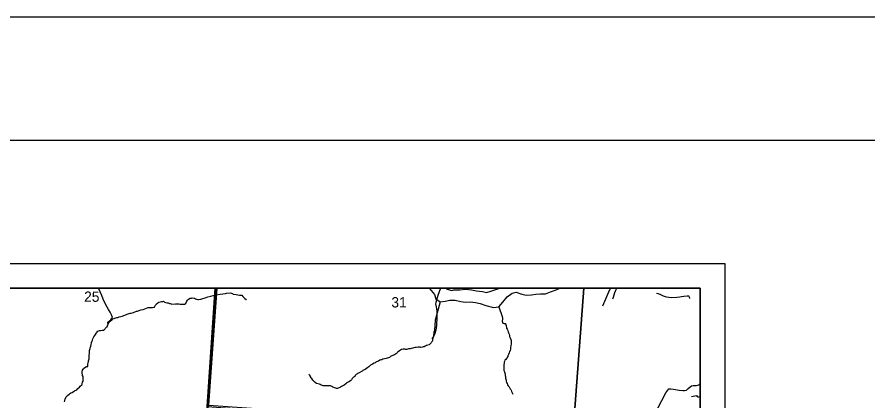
# Model space of a CAD drawing. Extents: x 0 to 34, y 0 to 22.
# Drawn here: x 6.132 to 9.58, y 20.443 to 22 of the extents above; entities that cross this region are included whole.
import ezdxf

# ---------------------------------------------------------------- set-up
doc = ezdxf.new("R2010")
doc.units = 0
for name, color, linetype in [('GM_X_Corporation', 7, 'Continuous'), ('GM_X_County_Road', 7, 'Continuous'), ('GM_X_Minor_River', 7, 'Continuous'), ('GM_X_Section_Text', 7, 'Continuous'), ('GM_X_Township_Road', 7, 'Continuous'), ('SH_Border', 7, 'Continuous'), ('SH_Data', 7, 'Continuous')]:
    doc.layers.add(name, color=color, linetype=linetype)

msp = doc.modelspace()

# ---------------------------------------------------------------- linework, layer by layer
at = {"layer": 'GM_X_Corporation'}
for points in [[(3.3441, 14.1), (8.9, 14.1), (8.9, 20.9), (2.1, 20.9), (2.1, 16.1353), (2.1457, 16.065), (2.3447, 15.6926), (2.4297, 15.5215), (2.465, 15.4504), (2.4884, 15.4033), (2.5769, 15.2135), (2.7849, 14.8403), (2.8931, 14.6544), (3.0297, 14.4867), (3.1386, 14.3654), (3.228, 14.2415)], [(6.9348, 20.9), (2.1, 20.9), (2.1, 19.6396), (2.105, 19.6393), (2.5886, 19.6074), (3.0215, 19.5789), (3.8201, 19.5262), (3.8692, 19.5228), (4.8375, 19.4557), (5.0201, 19.4401), (5.6539, 19.3859), (5.9419, 19.3649), (6.5423, 19.3229), (6.824, 19.3005), (6.835, 19.4037), (6.8961, 20.3303), (6.9032, 20.4198)], [(6.9414, 20.9), (5.9334, 20.9), (5.901, 20.4176), (6.9011, 20.3385), (6.9084, 20.4264)], [(8.9, 20.2763), (8.9, 20.9), (6.9348, 20.9), (6.9032, 20.4198), (8.0028, 20.34), (8.3805, 20.3169), (8.59, 20.3005)], [(8.4295, 20.9), (6.9414, 20.9), (6.9084, 20.4264), (8.0074, 20.3484), (8.3851, 20.3217)], [(8.9, 20.285), (8.9, 20.9), (8.4295, 20.9), (8.3851, 20.3217)]]:
    msp.add_lwpolyline(points, close=True, dxfattribs=at)
at = {"layer": 'GM_X_County_Road'}
for points in [[(7.8703, 20.9), (7.8765, 20.8966), (7.8924, 20.8915), (7.8984, 20.8923)], [(7.8984, 20.8923), (7.9024, 20.8929), (7.9271, 20.894), (7.9499, 20.8959), (7.9735, 20.8936), (7.9943, 20.889), (8.0183, 20.8863), (8.0342, 20.8825), (8.0528, 20.8875), (8.0718, 20.8947), (8.0894, 20.9)], [(8.6142, 20.3116), (8.6222, 20.3154), (8.6587, 20.3383), (8.6939, 20.3635), (8.7082, 20.3797), (8.7282, 20.4138), (8.7614, 20.4759), (8.774, 20.4915)], [(8.774, 20.4915), (8.7814, 20.4925), (8.7928, 20.4907), (8.8157, 20.4862), (8.8297, 20.485), (8.8368, 20.485), (8.8451, 20.4869), (8.8513, 20.4928), (8.8593, 20.5008), (8.8653, 20.5044), (8.8722, 20.5057), (8.8852, 20.5062), (8.895, 20.5088), (8.9, 20.5135)]]:
    msp.add_lwpolyline(points, dxfattribs=at)
at = {"layer": 'GM_X_Minor_River'}
for points in [[(6.5013, 20.7528), (6.5009, 20.7625), (6.5123, 20.7715), (6.5194, 20.781), (6.5153, 20.7916), (6.5092, 20.803), (6.5036, 20.8132), (6.4979, 20.8231), (6.4877, 20.8409), (6.4816, 20.856), (6.476, 20.8708), (6.4691, 20.8856), (6.4631, 20.9)], [(7.8029, 20.9), (7.8102, 20.8915), (7.8238, 20.874), (7.829, 20.8565), (7.8464, 20.8451), (7.8669, 20.8473), (7.8858, 20.8518), (7.9078, 20.8518), (7.9304, 20.8464), (7.9494, 20.8433), (7.9683, 20.8448), (7.9902, 20.8424), (8.0091, 20.8378), (8.0318, 20.8302), (8.0628, 20.8225), (8.084, 20.824), (8.1007, 20.8429), (8.119, 20.8656), (8.138, 20.8799), (8.1554, 20.8837), (8.1781, 20.8753), (8.1955, 20.8722), (8.2174, 20.8729), (8.2348, 20.8766), (8.2538, 20.8773)], [(8.2538, 20.8773), (8.2742, 20.878), (8.2939, 20.8855), (8.3166, 20.8938), (8.3313, 20.9)], [(8.5061, 20.8284), (8.5348, 20.8945), (8.5396, 20.9)], [(6.7301, 20.844), (6.7402, 20.8408), (6.7448, 20.8403), (6.7497, 20.8387), (6.7527, 20.8375), (6.7572, 20.8363), (6.7598, 20.8359), (6.775, 20.8368), (6.7886, 20.8365), (6.7935, 20.8353), (6.7966, 20.8349), (6.8026, 20.8348), (6.8121, 20.8357), (6.8152, 20.8372), (6.8182, 20.8402), (6.821, 20.8477), (6.8234, 20.8511), (6.8269, 20.8556), (6.8341, 20.8593), (6.8391, 20.8604), (6.8417, 20.8607), (6.8512, 20.8594), (6.8553, 20.8574), (6.859, 20.8555), (6.8651, 20.8546), (6.8681, 20.8545), (6.8768, 20.8555), (6.8807, 20.857), (6.8986, 20.8624), (6.905, 20.8645), (6.9172, 20.8685), (6.9275, 20.8702), (6.9347, 20.872), (6.94, 20.8738), (6.956, 20.8766), (6.9769, 20.8793), (6.9811, 20.8807), (6.9955, 20.8809), (7.0019, 20.8796), (7.0049, 20.8792), (7.0087, 20.8765), (7.02, 20.8744), (7.0343, 20.8722), (7.043, 20.8721), (7.0471, 20.8667), (7.056, 20.8578), (7.0609, 20.8539), (7.0618, 20.8534)], [(6.3966, 20.5113), (6.397, 20.5139), (6.3982, 20.5188), (6.3998, 20.5234), (6.4011, 20.5305), (6.4011, 20.534), (6.4005, 20.5393), (6.3998, 20.5423), (6.3983, 20.5458), (6.3976, 20.55), (6.3965, 20.5527), (6.3958, 20.5557), (6.3963, 20.561), (6.3975, 20.5671), (6.401, 20.5719), (6.4015, 20.5746), (6.4068, 20.5779), (6.4145, 20.5824), (6.419, 20.5827), (6.4195, 20.5853), (6.4196, 20.5914), (6.4212, 20.5986), (6.4216, 20.602), (6.4225, 20.6058), (6.4233, 20.6092), (6.4241, 20.6141), (6.425, 20.6179), (6.4251, 20.627), (6.4257, 20.6368), (6.4261, 20.6399), (6.4266, 20.6478), (6.4283, 20.655), (6.4291, 20.6577), (6.4299, 20.6607), (6.4311, 20.6656), (6.4323, 20.6721), (6.4343, 20.677), (6.4348, 20.68), (6.4372, 20.6872), (6.4376, 20.6898), (6.4396, 20.6951), (6.4427, 20.7004), (6.4435, 20.703), (6.4474, 20.7079), (6.4509, 20.712), (6.4532, 20.7161), (6.4544, 20.7192), (6.4598, 20.7263), (6.4667, 20.7284), (6.4705, 20.7291), (6.478, 20.7294), (6.4807, 20.7301), (6.4845, 20.7304), (6.4887, 20.7334), (6.4899, 20.7364), (6.4946, 20.7424), (6.4972, 20.7439), (6.4988, 20.748), (6.5008, 20.751), (6.502, 20.7552), (6.504, 20.7597), (6.5074, 20.7635), (6.5094, 20.7665), (6.5175, 20.7732), (6.5213, 20.7754), (6.5255, 20.7776), (6.5285, 20.7787), (6.5373, 20.7816), (6.5403, 20.7819), (6.5464, 20.7841), (6.5529, 20.7851), (6.5579, 20.7873), (6.5697, 20.7905), (6.5723, 20.7923), (6.583, 20.7963), (6.5868, 20.797), (6.591, 20.7985), (6.5948, 20.7992), (6.6043, 20.8013), (6.6165, 20.8068), (6.6211, 20.8075), (6.628, 20.8104), (6.634, 20.8122), (6.6432, 20.8139), (6.6508, 20.8168), (6.6634, 20.8216), (6.6694, 20.8222), (6.6725, 20.8222), (6.6755, 20.8217), (6.6808, 20.8216), (6.6888, 20.8234), (6.6911, 20.8272), (6.6916, 20.8298), (6.6942, 20.8321), (6.6962, 20.8354), (6.7031, 20.8414), (6.7077, 20.8436), (6.7176, 20.8461), (6.7233, 20.8468), (6.726, 20.8475), (6.7301, 20.844)], [(7.8464, 20.8451), (7.8272, 20.7706), (7.8268, 20.7676), (7.826, 20.7638), (7.8254, 20.7562), (7.8246, 20.7517), (7.8249, 20.7479), (7.8248, 20.7414), (7.8243, 20.7369), (7.8239, 20.732), (7.8223, 20.7255), (7.8218, 20.7217), (7.8213, 20.716), (7.8205, 20.7111), (7.8193, 20.7058), (7.8176, 20.7005), (7.8168, 20.6967), (7.8164, 20.6941), (7.8152, 20.6884), (7.814, 20.6846), (7.812, 20.6813), (7.8108, 20.6782), (7.8066, 20.6741), (7.802, 20.6704), (7.7963, 20.669), (7.7921, 20.6672), (7.7875, 20.6657), (7.7848, 20.6646), (7.7818, 20.6628), (7.7783, 20.6621), (7.7757, 20.661), (7.7692, 20.6603), (7.7654, 20.6604), (7.7571, 20.6609), (7.7491, 20.6595), (7.7457, 20.6592), (7.74, 20.6582), (7.7358, 20.6567), (7.729, 20.6553), (7.7248, 20.6546), (7.7191, 20.654), (7.7115, 20.6522), (7.7069, 20.6519), (7.7035, 20.6523), (7.6998, 20.6524), (7.6967, 20.6525), (7.6922, 20.6518), (7.6895, 20.6511), (7.6857, 20.6485), (7.6822, 20.6459), (7.6772, 20.6425), (7.6742, 20.6411), (7.6722, 20.6384), (7.6699, 20.6351), (7.6657, 20.6329), (7.6619, 20.6299), (7.6516, 20.6259), (7.6458, 20.6226), (7.6412, 20.6188), (7.6279, 20.6149), (7.6146, 20.6117), (7.6104, 20.6102), (7.6066, 20.6099), (7.602, 20.6077), (7.5966, 20.604), (7.5883, 20.6019), (7.5856, 20.6), (7.5829, 20.5974), (7.5798, 20.5956), (7.5729, 20.5919), (7.5645, 20.5875), (7.5599, 20.5841), (7.5572, 20.5815), (7.5542, 20.5789), (7.5434, 20.5704), (7.5339, 20.5667), (7.5315, 20.5637), (7.5163, 20.556), (7.5117, 20.5546), (7.509, 20.5516), (7.5063, 20.5497), (7.5028, 20.5464), (7.5012, 20.5422), (7.4955, 20.54), (7.4936, 20.5367), (7.4905, 20.5344)], [(8.084, 20.824), (8.0987, 20.785), (8.0993, 20.7789), (8.0989, 20.7748), (8.0987, 20.766), (8.099, 20.7622), (8.1012, 20.7588), (8.1065, 20.7575), (8.1107, 20.7567), (8.1129, 20.7525), (8.1139, 20.7483), (8.1153, 20.7384), (8.1182, 20.7342), (8.1201, 20.7307), (8.1204, 20.7281), (8.1226, 20.7227), (8.1236, 20.7193), (8.1258, 20.7139), (8.1272, 20.7082), (8.1279, 20.7048), (8.1298, 20.7013), (8.1305, 20.6986), (8.133, 20.6925), (8.1348, 20.6887), (8.1346, 20.6739), (8.1337, 20.6663), (8.1321, 20.661), (8.1316, 20.6568), (8.1312, 20.6538), (8.1299, 20.6466), (8.1276, 20.6429), (8.1264, 20.6383), (8.1244, 20.6315), (8.122, 20.6285), (8.1216, 20.6259), (8.1208, 20.6232), (8.1173, 20.6172), (8.1157, 20.6146), (8.1126, 20.6105), (8.1092, 20.6079), (8.1072, 20.6033), (8.1068, 20.5999), (8.1063, 20.5961), (8.1051, 20.5897), (8.1046, 20.5863), (8.1042, 20.5832), (8.1042, 20.5806), (8.1048, 20.576), (8.1051, 20.5711), (8.1054, 20.5658), (8.1076, 20.5615), (8.1097, 20.5513), (8.1107, 20.5459), (8.1118, 20.5425), (8.1117, 20.5383), (8.1121, 20.5349), (8.1131, 20.5311), (8.1138, 20.5269), (8.1149, 20.5227), (8.1156, 20.5181), (8.1181, 20.5143), (8.1196, 20.5089), (8.1225, 20.5043), (8.127, 20.4997), (8.1284, 20.497), (8.131, 20.4924), (8.1332, 20.4893), (8.1343, 20.4863), (8.1365, 20.4817), (8.1383, 20.4759), (8.1401, 20.4725), (8.1408, 20.4698)], [(7.4905, 20.5344), (7.4885, 20.5314), (7.4881, 20.5288), (7.485, 20.5258), (7.4789, 20.5213), (7.4713, 20.5177), (7.4674, 20.5151), (7.4644, 20.5128), (7.4586, 20.5072), (7.4521, 20.5043), (7.4475, 20.5014), (7.4433, 20.4984), (7.4406, 20.4973), (7.4341, 20.4944), (7.4307, 20.4929), (7.4276, 20.4933), (7.4239, 20.4945), (7.4186, 20.4965), (7.4118, 20.4993), (7.4085, 20.5013), (7.4021, 20.5036), (7.3831, 20.504), (7.3794, 20.5044), (7.3756, 20.5041), (7.3729, 20.5045), (7.3699, 20.5061), (7.3654, 20.5069), (7.3609, 20.5097), (7.3575, 20.5109), (7.3454, 20.5141), (7.3417, 20.5168), (7.3395, 20.5195), (7.3353, 20.5215), (7.3331, 20.5242), (7.3309, 20.5276), (7.3265, 20.5338), (7.3239, 20.5369), (7.322, 20.5403), (7.321, 20.5438), (7.3177, 20.5495), (7.3162, 20.5521)], [(6.3252, 20.4399), (6.3257, 20.4445), (6.3261, 20.4479), (6.3269, 20.4505), (6.3313, 20.46), (6.337, 20.4644), (6.3432, 20.47), (6.3509, 20.4756), (6.3558, 20.477), (6.3612, 20.4815), (6.3654, 20.4833), (6.3746, 20.4885), (6.3788, 20.4933), (6.3861, 20.4993), (6.3881, 20.5027), (6.3946, 20.5079), (6.3966, 20.5113)], [(8.8656, 20.4607), (8.885, 20.4645), (8.8884, 20.461), (8.891, 20.4595), (8.8948, 20.459), (8.9, 20.4607)]]:
    msp.add_lwpolyline(points, dxfattribs=at)
at = {"layer": 'GM_X_Township_Road'}
for points in [[(7.8486, 20.9), (7.8381, 20.8699), (7.8314, 20.8511), (7.8288, 20.8422), (7.8281, 20.8366), (7.8303, 20.8248), (7.8333, 20.807), (7.8333, 20.7822), (7.8318, 20.7493), (7.8288, 20.7305), (7.8255, 20.7171), (7.8192, 20.7038), (7.8136, 20.6946)], [(8.5467, 20.8567), (8.5494, 20.8643), (8.5546, 20.8825), (8.5582, 20.8921), (8.5627, 20.9)], [(8.7238, 20.8797), (8.7306, 20.8783), (8.7399, 20.8744), (8.7509, 20.8695), (8.758, 20.8668), (8.7638, 20.8651), (8.7732, 20.8636), (8.7844, 20.863), (8.8055, 20.8638), (8.8173, 20.8651), (8.8251, 20.8667), (8.8342, 20.8685), (8.8479, 20.8694), (8.8536, 20.8686), (8.8548, 20.8675), (8.8558, 20.8658), (8.8575, 20.8579)]]:
    msp.add_lwpolyline(points, dxfattribs=at)
at = {"layer": 'SH_Border'}
msp.add_lwpolyline([(1.5, 21.5), (33.5, 21.5), (33.5, 0.5), (1.5, 0.5)], close=True, dxfattribs=at)
at = {"layer": 'SH_Data'}
for p, q in [((2, 21), (9, 21)), ((9, 21), (9, 14)), ((2.1, 20.9), (8.9, 20.9)), ((8.9, 20.9), (8.9, 14.1))]:
    msp.add_line(p, q, dxfattribs=at)
msp.add_lwpolyline([(0, 0), (34, 0), (34, 22), (0, 22)], close=True, dxfattribs=at)

# ---------------------------------------------------------------- texts
at = {"layer": 'GM_X_Section_Text'}
for s, p in [('25', (6.4042, 20.8449)), ('31', (7.6492, 20.822))]:
    msp.add_text(s, height=0.04186, rotation=0, dxfattribs=at).set_placement(p)

doc.saveas('drawing.dxf')
